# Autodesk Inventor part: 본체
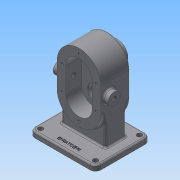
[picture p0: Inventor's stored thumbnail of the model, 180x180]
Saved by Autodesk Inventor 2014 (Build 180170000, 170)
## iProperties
Created: 2020-09
Part Number: 본체
Material: 일반
Document SubType Name: Modeling
Designer: net
Density: 1 g/cm^3
Appearance: 기본값
Author: net
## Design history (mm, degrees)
sketch "스케치1"
  geometry: L1 (-60, -50)-(60, -50); L2 (60, -50)-(60, 50); L3 (60, 50)-(-60, 50); L4 (-60, 50)-(-60, -50); L5 (-60, -50)-(60, 50); L6 (60, -50)-(-60, 50); 1 further point
  constraints: 12 end point, 2 midpoint, 2 parallel, 1 horizontal, 1 perpendicular
  dimensions: "d0" = 120 distance of L2.end L3.end; "d1" = 100 distance of L3.end L1.start
extrude "돌출1" new body sketch "스케치1" distance "d2" = 10; taper "d3" = 0 deg
sketch "스케치3"
  geometry: L1 (60, 50)-(-60, 50) reference; L2 (-40, -12)-(40, -12); L3 (40, -12)-(40, 25); L4 (40, 25)-(-40, 25); L5 (-40, 25)-(-40, -12); L6 (-40, -12)-(40, 25); L7 (40, -12)-(-40, 25); 3 further points
  constraints: 12 end point, 3 midpoint, 2 parallel, 1 horizontal, 1 perpendicular, 1 vertical alignment
  dimensions: "d4" = 80 distance of L3.end L4.end; "d5" = 37 distance of L2.end L3.end; "d6" = 25 distance between parallel lines of L1 L4
extrude "돌출2" join sketch "스케치3" distance "d7" = 80; taper "d8" = 0 deg
sketch "스케치4"
  geometry: L1 (-40, -12)-(40, -12) reference; L2 (40, -12)-(40, 25) reference; L3 (40, 25)-(-40, 25) reference; L4 (-40, 25)-(-40, -12) reference; L5 (-40, 6.5)-(40, 6.5); 1 further point
  constraints: 2 end point, 2 midpoint
sketch "스케치5"
  geometry: L1 (0, 37)-(0, 0) reference; L2 (0, 37)-(-80, 37) reference; L3 (-80, 0)-(-80, 37) reference; L4 (0, 0)-(-80, 0) reference; L5 (-80, 18.5)-(0, 18.5); 1 further point
  constraints: 2 end point, 2 midpoint
node "작업 평면1"
sketch "스케치6"
  geometry: L1 (40, 22)-(40, -22); L2 (80, 22)-(80, -22); L3 (0, -22)-(0, 22); L4 (0, 0)-(80, 0) reference; A1 r 40 centre (40, 22) between (80, 22) and (0, 22); A2 r 40 centre (40, -22) between (0, -22) and (80, -22); 4 further points
  constraints: 8 end point, 4 point on circle, 4 tangent, 3 midpoint, 2 centre point, 2 coincident, 1 parallel, 1 vertical, 1 vertical alignment
  dimensions: "d9" = 22 distance of point (40, 0) L1.end; "d10" = 40 radius of A2
extrude "돌출3" join sketch "스케치6" distance "d11" = 26.5; taper "d13" = 0 deg; dims "d12" = 26.5, "d14" = 0
sketch "스케치7"
  geometry: L1 (80, -22)-(80, 22) reference; L2 (40, -22)-(40, 22); L3 (16, -22)-(16, 22); L4 (64, 22)-(64, -22); A1 r 40 centre (40, 22) between (80, 22) and (0, 22) reference; A2 r 40 centre (40, -22) between (0, -22) and (80, -22) reference; A3 r 24 centre (40, -22) between (16, -22) and (64, -22); A4 r 24 centre (40, 22) between (64, 22) and (16, 22); 2 further points
  constraints: 8 end point, 4 point on circle, 4 tangent, 2 centre point, 2 parallel, 1 coincident, 1 midpoint
  dimensions: "d15" = 24 radius of A4
extrude "돌출4" cut sketch "스케치7" distance "d16" = 29; taper "d17" = 0 deg
sketch "스케치8"
  geometry: C1 r 12.5 at (40, 22); C2 r 12.5 at (40, -22); A1 r 24 centre (40, -22) between (16, -22) and (64, -22) reference; A2 r 24 centre (40, 22) between (64, 22) and (16, 22) reference; 1 further point
  constraints: 2 centre point, 2 coincident
  dimensions: "d18" = 25 diameter of C1; "d19" = 25 diameter of C2
extrude "돌출5" cut sketch "스케치8" distance "d20" = 15; taper "d21" = 0 deg
chamfer "모따기1" distance "d22" = 1; stored, may be unused: second distance "d23" = 2, angle "d24" = 45 deg
fillet "모깎기1" dims "d25" = 10
fillet "모깎기2" dims "d26" = 3
fillet "모깎기3" dims "d27" = 3
fillet "모깎기4" dims "d28" = 3
fillet "모깎기5" dims "d29" = 3
sketch "스케치9"
  geometry: C1 r 19 at (40, -22); A1 r 37 centre (40, -22) between (3, -22) and (77, -22) reference; 1 further point
  constraints: 1 centre point, 1 coincident
  dimensions: "d30" = 38 diameter of C1
extrude "돌출6" join sketch "스케치9" distance "d31" = 17; taper "d32" = 0 deg
fillet "모깎기6" dims "d33" = 3
sketch "스케치10"
  geometry: C1 r 19 at (0, 0) reference; C2 r 14 at (0, 0); 1 further point
  constraints: 1 centre point, 1 coincident
  dimensions: "d34" = 28 diameter of C2
extrude "돌출7" cut sketch "스케치10" distance "d35" = 7.3; taper "d36" = 0 deg
sketch "스케치11"
  geometry: C1 r 12.5 at (0, 0) reference; C2 r 8.5 at (0, 0); 1 further point
  constraints: 1 centre point, 1 coincident
  dimensions: "d37" = 17 diameter of C2
extrude "돌출8" cut sketch "스케치11" stored distance "d38" = 7.3; taper "d39" = 0 deg
sketch "스케치12"
  geometry: L1 (50, 93)-(50, 131) reference; L2 (50, 112)-(0, 112); L3 (50, 126)-(42.7, 126) reference; L4 (50, 126)-(49.3, 126); L5 (49.3, 126)-(50, 126.404); L6 (50, 126)-(50, 126.404); 1 further point
  constraints: 8 end point, 2 point on line, 1 collinear, 1 midpoint, 1 perpendicular
  dimensions: "d40" = 30 deg angle of L4 L5; "d41" = 0.7 distance of L3.start L4.end
revolve "회전1" sketch "스케치12" stored, may be unused: angle "d42" = 90 deg
fillet "모깎기7" dims "d43" = 0.5
sketch "스케치13"
  geometry: L1 (0, 22)-(0, -22) reference; L2 (40, 22)-(40, 53); L3 (40, 22)-(9, 22); L4 (40, 22)-(71, 22); L5 (40, -22)-(9, -22); L6 (40, -22)-(71, -22); L7 (40, -22)-(40, -53); A1 r 40 centre (40, 22) between (80, 22) and (0, 22) reference; A2 r 40 centre (40, -22) between (0, -22) and (80, -22) reference; A3 r 31 centre (40, 22) between (40, 53) and (9, 22); A4 r 31 centre (40, -22) between (9, -22) and (71, -22); 1 further point
  constraints: 12 end point, 6 point on circle, 2 centre point, 2 coincident, 2 collinear, 2 parallel, 2 perpendicular
  dimensions: "d44" = 62 diameter of A3; "d45" = 62 diameter of A4
hole "구멍1" sketch "스케치13" at (40, 53), (9, 22), (71, 22), (9, -22), (71, -22), (40, -53) diameter "d46" = 4.134; stored, may be unused: countersink angle "d50" = 90 deg, drill point angle "d52" = 118 deg; dims "d47" = 10, "d48" = 4, "d49" = 2, "d51" = 12
sketch "스케치14"
  geometry: C1 r 4.5 at (-50, 40); C2 r 4.5 at (-50, -40); C3 r 4.5 at (50, -40); C4 r 4.5 at (50, 40); A1 r 7 centre (50, 40) between (57, 40) and (50, 47) reference; A2 r 7 centre (-50, 40) between (-50, 47) and (-57, 40) reference; A3 r 7 centre (-50, -40) between (-57, -40) and (-50, -47) reference; A4 r 7 centre (50, -40) between (50, -47) and (57, -40) reference; 1 further point
  constraints: 4 centre point, 4 coincident, 3 equal radius
  dimensions: "d53" = 9 diameter of C1
extrude "돌출9" cut sketch "스케치14" stored distance "d54" = 7.3; taper "d55" = 0 deg
sketch "스케치15"
  geometry: L1 (44, 0)-(0, 0) reference; L2 (112, -20)-(112, 60) reference; C1 r 11 at (22, 14); 1 further point
  constraints: 1 centre point
  dimensions: "d56" = 90 distance from line of L2 C1.centre; "d57" = 14 distance from line of L1 C1.centre; "d58" = 22 diameter of C1
extrude "돌출10" join sketch "스케치15" distance "d59" = 10; taper "d60" = 0 deg
fillet "모깎기8" dims "d61" = 3
sketch "스케치16"
  geometry: C1 r 11 at (0, 0) reference; 1 further point
hole "구멍2" sketch "스케치16" at (0, 0) diameter "d62" = 8.376; stored, may be unused: countersink angle "d66" = 90 deg, drill point angle "d68" = 118 deg; dims "d63" = 10, "d64" = 4, "d65" = 2, "d67" = 12
sketch "스케치17"
  geometry: C1 r 11 at (0, 0) reference; 1 further point
hole "구멍3" sketch "스케치17" at (0, 0) diameter "d69" = 8.376; stored, may be unused: countersink angle "d73" = 90 deg, drill point angle "d75" = 118 deg; dims "d70" = 10, "d71" = 4, "d72" = 2, "d74" = 12
sketch "스케치18"
  geometry: L1 (-50, -50)-(50, -50) reference; L2 (-60, 40)-(-60, -40) reference; 2 further points
  constraints: 1 other
  dimensions: "d76" = 12 distance from line of L1 point (0, -38); "d77" = 60 distance from line of L2 point (0, -38)
extrude "돌출11" join sketch "스케치18" distance "d78" = 0.5; taper "d79" = 0 deg
node "솔리드1"
mirror "대칭1"
